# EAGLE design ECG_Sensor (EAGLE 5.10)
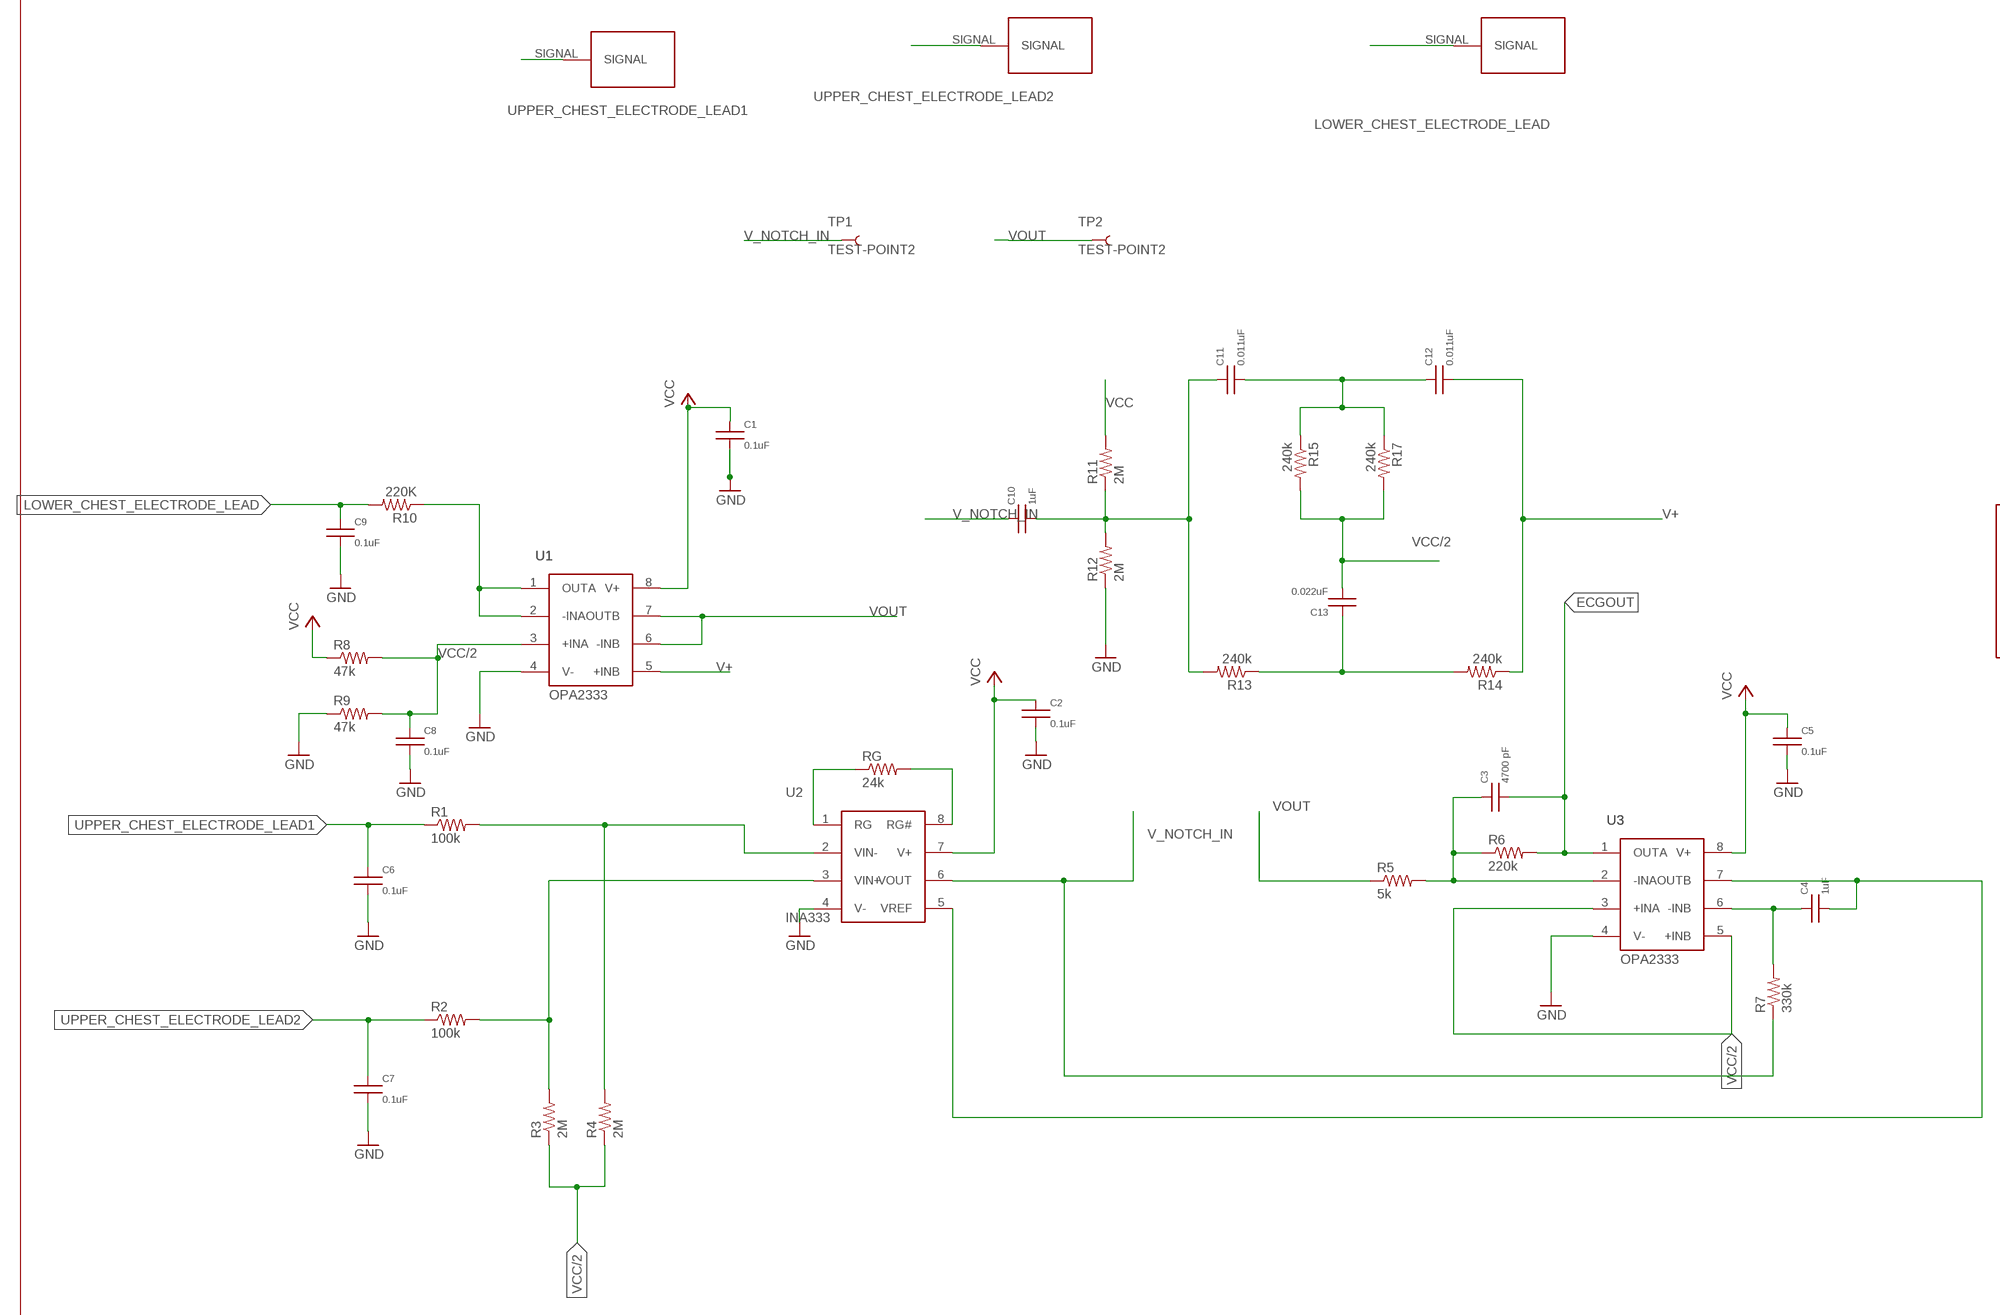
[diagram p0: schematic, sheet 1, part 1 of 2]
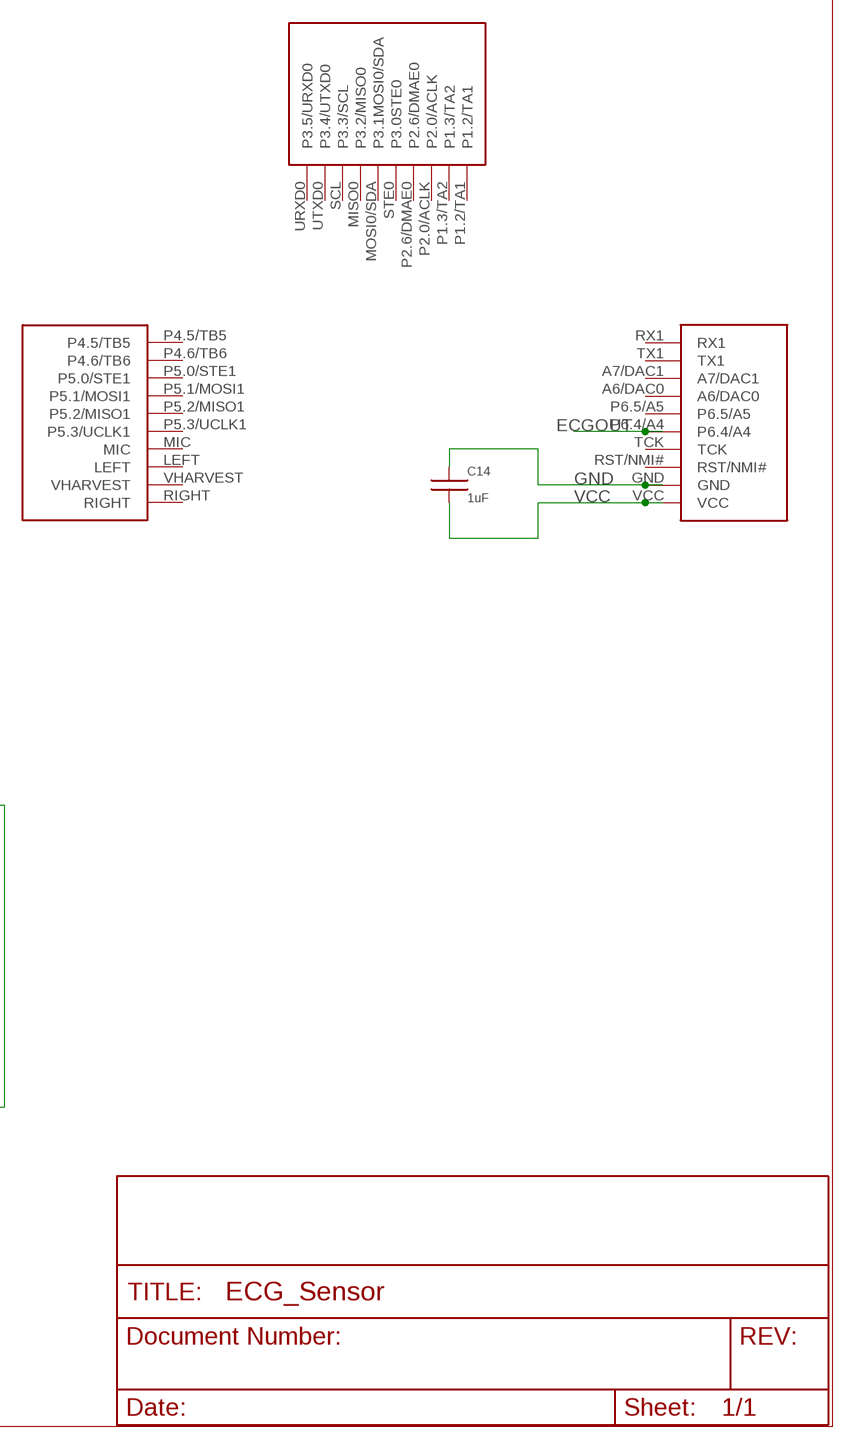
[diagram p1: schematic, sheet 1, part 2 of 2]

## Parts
BLACK  PLASTICJACKNEW  [PLASTICJACKNEW]
C1  0.1uF  C0603  [C0603]
C2  0.1uF  C0603  [C0603]
C3  4700 pF  C0603  [C0603]
C4  1uF  C0603  [C0603]
C5  0.1uF  C0603  [C0603]
C6  0.1uF  C0603  [C0603]
C7  0.1uF  C0603  [C0603]
C8  0.1uF  C0603  [C0603]
C9  0.1uF  C0603  [C0603]
C10  1uF  C0603  [C0603]
C11  0.011uF  C1206  [C1206]
C12  0.011uF  C1206  [C1206]
C13  0.022uF  C1206  [C1206]
C14  1uF  C0603  [C0603]
J4  HIJACK-INTERFACE  [HIJACK-INTERFACE-30PIN]
R1  100k  R-US_R0603  [R0603]
R2  100k  R-US_R0603  [R0603]
R3  2M  R-US_R0603  [R0603]
R4  2M  R-US_R0603  [R0603]
R5  5k  R-US_R0603  [R0603]
R6  220k  R-US_R0603  [R0603]
R7  330k  R-US_R0603  [R0603]
R8  47k  R-US_R0603  [R0603]
R9  47k  R-US_R0603  [R0603]
R10  220K  R-US_R0603  [R0603]
R11  2M  R-US_R0603  [R0603]
R12  2M  R-US_R0603  [R0603]
R13  240k  R-US_R0603  [R0603]
R14  240k  R-US_R0603  [R0603]
R15  240k  R-US_R0603  [R0603]
R17  240k  R-US_R0603  [R0603]
RED  PLASTICJACKNEW  [PLASTICJACKNEW]
RG  24k  R-US_R0603  [R0603]
TP1  TEST-POINT2  [PAD.02X.02]
TP2  TEST-POINT2  [PAD.02X.02]
U1  OPA2333  [SOIC]
U2  INA333  [MSOP8]
U3  OPA2333  [SOIC]
WHITE  PLASTICJACKNEW  [PLASTICJACKNEW]

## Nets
ECGOUT: C3.2 J4.P6.4/A4 R6.2 U3.1(OUTA)
GND: C1.2 C2.2 C5.2 C6.2 C7.2 C8.2 C9.2 C14.1 J4.GND R9.1 R12.1 U1.4(V-) U2.4(V-) U3.4(V-)
LOWER_CHEST_ELECTRODE_LEAD: BLACK.SIGNAL C9.1 R10.2
N$2: R10.1 U1.1(OUTA) U1.2(-INA)
N$4: RG.1 U2.1(RG)
N$5: RG.2 U2.8(RG#)
N$6: R1.2 R4.2 U2.2(VIN-)
N$7: C11.2 C12.1 R15.1 R17.1
N$8: R2.2 R3.2 U2.3(VIN+)
N$10: C10.2 C11.1 R11.1 R12.2 R13.2
N$12: C13.1 R13.1 R14.2
N$13: C3.1 R5.2 R6.1 U3.2(-INA)
N$17: C4.1 R7.2 U3.6(-INB)
UPPER_CHEST_ELECTRODE_LEAD1: C6.1 R1.1 RED.SIGNAL
UPPER_CHEST_ELECTRODE_LEAD2: C7.1 R2.1 WHITE.SIGNAL
V+: C12.2 R14.1 U1.5(+INB)
V_NOTCH_IN: C10.1 R7.1 TP1.P$1 U2.6(VOUT)
VCC: C1.1 C2.1 C5.1 C14.2 J4.VCC R8.1 R11.2 U1.8(V+) U2.7(V+) U3.8(V+)
VCC/2: C8.1 C13.2 R3.1 R4.1 R8.2 R9.2 R15.2 R17.2 U1.3(+INA) U3.3(+INA) U3.5(+INB)
VOUT: R5.1 TP2.P$1 U1.6(-INB) U1.7(OUTB)
VREF: C4.2 U2.5(VREF) U3.7(OUTB)
Unconnected: J4.A6/DAC0 J4.A7/DAC1 J4.LEFT J4.MIC J4.MISO0(P3.2/MISO0) J4.MOSI0/SDA(P3.1MOSI0/SDA) J4.P1.2/TA1 J4.P1.3/TA2 J4.P2.0/ACLK J4.P2.6/DMAE0 J4.P4.5/TB5 J4.P4.6/TB6 J4.P5.0/STE1 J4.P5.1/MOSI1 J4.P5.2/MISO1 J4.P5.3/UCLK1 J4.P6.5/A5 J4.RIGHT J4.RST/NMI# J4.RX1 J4.SCL(P3.3/SCL) J4.STE0(P3.0STE0) J4.TCK J4.TX1 J4.URXD0(P3.5/URXD0) J4.UTXD0(P3.4/UTXD0) J4.VHARVEST

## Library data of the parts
BLACK RED WHITE = sonal:PLASTICJACKNEW
C1-C14 = umich:C
J4 = umich:HIJACK-INTERFACE
R1-R15 R17 RG = rcl:R-US_: RESISTOR, American symbol
TP1 TP2 = SparkFun:TEST-POINT
U1 U3 = sonal:OPA2333
U2 = sonal:INA333

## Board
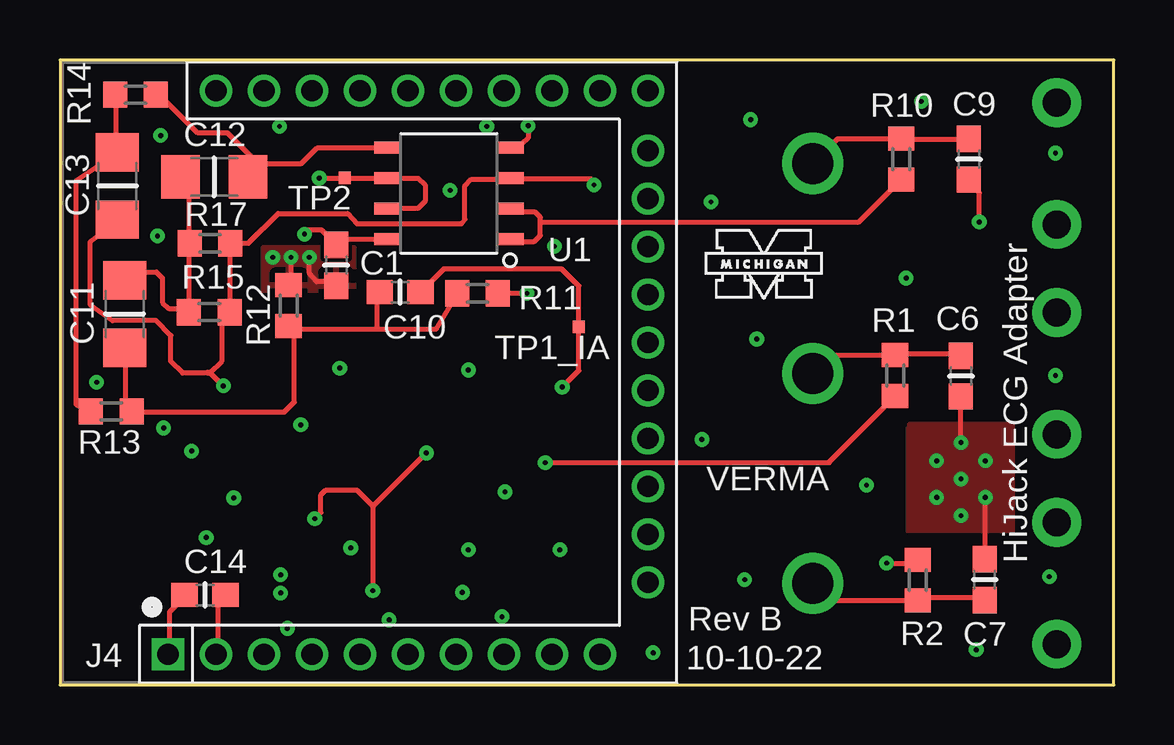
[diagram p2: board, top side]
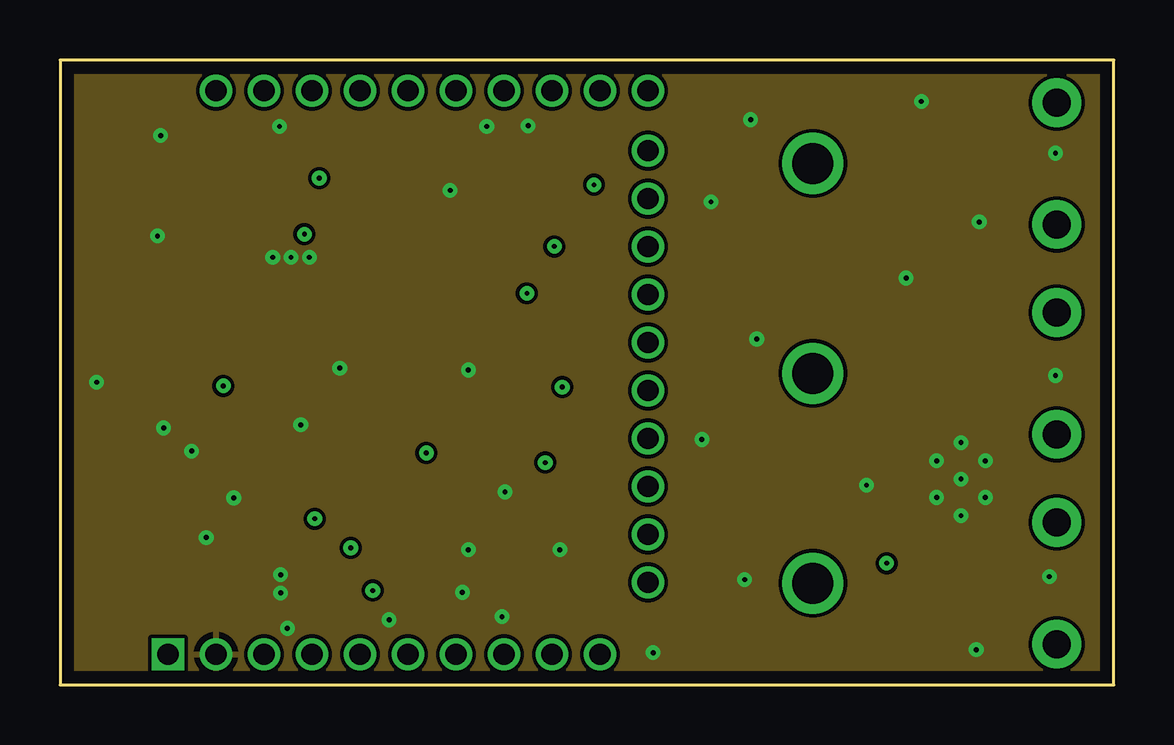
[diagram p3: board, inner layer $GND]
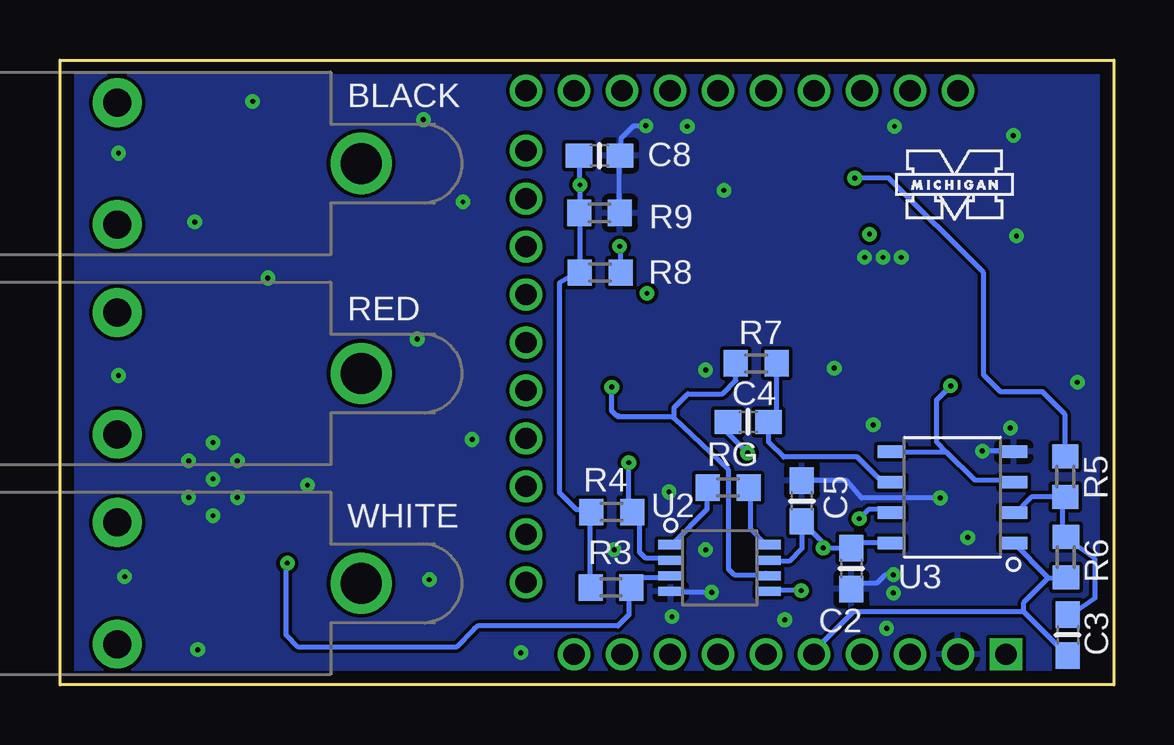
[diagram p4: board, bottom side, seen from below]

Size 43.92 x 26.06 mm. Coordinates in mm from the lower left corner, seen from the top.
Outline: 0,0 43.92,0 43.92,26.06 0,26.06 0,0
Copper layers (1+2*15+16): Top 0.0178mm / dielectric 0.3048mm / $GND 0.0356mm / dielectric 0.7112mm / $VCC 0.0356mm / dielectric 0.3048mm / Bottom 0.0178mm
Design rules "SSC-EAGLE-4Lyr_v1.0.0.3": minimum track width 6mil, minimum drill 8mil, track to track 6mil, track to pad 6mil, pad to pad 6mil, via to via 6mil, smd to smd 6mil, copper to edge 20mil, drill to drill 16mil, minimum pad ring 8mil, minimum via ring 8mil, stop-mask expansion 3mil, vias tented up to drill 0mil, thermal gap 10mil

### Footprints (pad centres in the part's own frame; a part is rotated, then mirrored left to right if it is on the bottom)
PLASTICJACKNEW = drill 1.168 pad 2.032 round: P$1 2.286,2.54; P$2 2.286,-2.54 | drill 1.702 pad 2.54 round: SIGNAL -7.874,0
C0603 = smd 1.1 x 1: 1 -0.85,0; 2 0.85,0
C1206 = smd 1.6 x 1.8: 1 -1.4,0; 2 1.4,0
HIJACK-INTERFACE-30PIN = drill 0.89 pad 1.346 round: A6/DAC0 2.89,-12.46; A7/DAC1 4.89,-12.46; GND -7.11,-12.46; LEFT -3.11,11.04; MIC -1.11,11.04; MISO0 10.89,2.54; MOSI0/SDA 10.89,0.54; P1.2/TA1 10.89,-9.46; P1.3/TA2 10.89,-7.46; P2.0/ACLK 10.89,-5.46; P2.6/DMAE0 10.89,-3.46; P4.5/TB5 10.89,11.04; P4.6/TB6 8.89,11.04; P5.0/STE1 6.89,11.04; P5.1/MOSI1 4.89,11.04; P5.2/MISO1 2.89,11.04; P5.3/UCLK1 0.89,11.04; P6.4/A4 -1.11,-12.46; P6.5/A5 0.89,-12.46; RIGHT -7.11,11.04; RST/NMI# -5.11,-12.46; RX1 8.89,-12.46; SCL 10.89,4.54; STE0 10.89,-1.46; TCK -3.11,-12.46; TX1 6.89,-12.46; URXD0 10.89,8.54; UTXD0 10.89,6.54; VHARVEST -5.11,11.04 | drill 0.89 pad 1.346 square: VCC -9.11,-12.46
R0603 = smd 1 x 1.1: 1 -0.85,0; 2 0.85,0
PAD.02X.02 = smd 0.508 x 0.508: P$1 0,0
SOIC = smd 0.51 x 1.143: 1 -1.905,-2.55; 2 -0.635,-2.55; 3 0.635,-2.55; 4 1.905,-2.55; 5 1.905,2.55; 6 0.635,2.55; 7 -0.635,2.55; 8 -1.905,2.55
MSOP8 = smd 0.38 x 1.016: 1 -0.975,-2.038; 2 -0.325,-2.038; 3 0.325,-2.038; 4 0.975,-2.038; 5 0.975,2.038; 6 0.325,2.038; 7 -0.325,2.038; 8 -0.975,2.038

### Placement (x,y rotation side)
BLACK  39.24,21.74 180 bottom
C1  11.51,17.5 270 top
C2  10.95,4.85 270 bottom
C3  1.93,2.08 270 bottom
C4  15.24,10.97 180 bottom
C5  13,7.67 90 bottom
C6  37.54,12.88 270 top
C7  38.53,4.39 90 top
C8  21.44,22.07 0 bottom
C9  37.87,21.92 270 top
C10  14.17,16.38 180 top
C11  2.69,15.47 90 top
C12  6.43,21.18 0 top
C13  2.39,20.8 270 top
C14  6.05,3.76 180 top
J4  13.61,13.74 0 top
R1  34.8,12.9 270 top
R2  35.74,4.37 90 top
R3  20.95,4.06 0 bottom
R4  20.93,7.21 0 bottom
R5  2.03,8.69 270 bottom
R6  2.01,5.33 270 bottom
R7  14.91,13.41 0 bottom
R8  21.41,17.2 180 bottom
R9  21.44,19.69 180 bottom
R10  35.05,21.92 90 top
R11  17.4,16.33 0 top
R12  9.52,15.82 270 top
R13  2.13,11.4 0 top
R14  3.15,24.61 180 top
R15  6.22,15.54 0 top
R17  6.25,18.41 0 top
RED  39.24,12.99 180 bottom
RG  16.08,8.23 0 bottom
TP1  21.62,14.94 0 top
TP2  11.86,21.14 0 top
U1  16.21,20.5 90 top
U2  16.43,4.88 270 bottom
U3  6.73,7.82 90 bottom
U$1  [UMICH]  26.8,15.9 0 top
U$2  [UMICH]  9.17,19.2 0 bottom
WHITE  39.24,4.24 180 bottom

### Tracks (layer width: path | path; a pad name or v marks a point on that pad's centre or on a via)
ECGOUT
  Bottom 0.203: 3.76,3.05 1.93,1.22 C3.2 | 4.17,5.89 U3.1 2.73,4.47 | R6.2 2.13,4.47 2.73,4.47 | 3.76,3.05 10.87,3.05 12.5,1.42 J4.P6.4/A4 | 2.73,4.47 3.76,3.44 3.76,3.05
GND  (via drill 0.2)
  Top 0.203: C6.2 37.69,11.99 37.54,11.84 v37.54,10.11 | 38.51,5.28 C7.2 38.56,5.27 v38.56,7.82 | C9.2 37.9,20.93 38.3,20.52 v38.3,19.3 | J4.GND 6.6,1.42 6.6,3.45 6.81,3.66 C14.1 7.01,3.86 | v19.51,23.32 19.51,22.81 18.97,22.3 18.59,22.56 U1.4 | R12.1 9.63,16.67 v9.63,17.83 | C1.2 11.51,16.71 11.4,16.82 10.69,16.82 10.39,17.17 v10.39,17.83
  Bottom 0.203: v16.76,3.86 18.39,3.86 U2.4 | R9.1 20.63,19.71 20.63,21.95 C8.2 20.42,22.15 20.52,22.25 20.52,22.81 20.02,23.32 v19.51,23.32 19.52,23.13 | v5.49,9.75 4.17,9.75 U3.4 | v9.2,4.6 9.53,4.6 9.86,4.27 10.68,4.27 C2.2 | v7.24,7.8 10.52,7.8 11.14,8.52 C5.2
  other vias: 36.53,9.35 37.54,8.59 38.56,9.35 36.53,7.82 37.54,7.06 9.19,3.84 8.86,17.83 17.02,5.64 18.54,8.05 20.83,5.64 11.65,13.21 6.1,6.15 4.32,10.72 17.78,23.29 9.14,23.29 4.19,22.91 4.06,18.72 10.03,10.85 1.52,12.62 28.52,4.39 24.71,1.35 38.18,1.47 41.22,4.52 41.48,12.9 41.48,22.17 28.78,23.57 29.03,14.43 35.26,16.97 33.6,8.33 26.75,10.24 35.89,24.33 17.02,13.13 16.26,20.62 27.13,20.14 9.47,2.36 18.41,2.84 13.72,2.72
  pour $GND: 0.28,25.83 43.69,25.83 43.61,0.15 0.36,0.25
  pour Top: 35.41,10.9 39.73,10.9 39.73,6.4 35.31,6.4 35.31,10.72 35.36,10.72 35.36,10.87
  pour Bottom: 8.59,4.9 9.86,4.9 9.86,3.51 8.59,3.51
  pour Top: 8.46,18.24 8.46,16.46 12.27,16.46 12.27,18.24
  pour Bottom: 43.74,25.76 43.74,25.7 43.69,25.7 43.69,0.2 0.36,0.2 0.28,25.81
LOWER_CHEST_ELECTRODE_LEAD
  Top 0.203: C9.1 37.69,22.76 R10.2 32.4,22.77 BLACK.SIGNAL
N$2
  Top 0.203: 18.8,18.69 U1.1 18.86,18.49 19.76,18.49 20.02,18.75 20.02,19.3 | U1.2 18.8,19.71 19.81,19.71 20.02,19.51 20.02,19.3 | 35.05,20.93 R10.1 33.29,19.3 20.02,19.3
N$4
  Bottom 0.203: U2.1 18.39,5.89 16.97,7.32 16.97,8.13 RG.1
N$5
  Bottom 0.203: U2.8 14.53,5.89 15.14,6.5 15.14,8.13 RG.2
N$6  (via drill 0.2)
  Top 0.203: 34.47,11.99 34.65,11.99 R1.2 32.06,9.31 32.06,9.27 v20.22,9.27
  Bottom 0.203: U2.2 18.59,5.28 19.51,5.28 19.76,5.54 19.76,6.9 R4.2 | R4.2 20.02,7.11 | v20.22,9.27 20.22,7.32 R4.2
N$7
  Top 0.203: C11.2 2.74,16.87 2.9,16.87 3.25,17.22 4.01,17.22 4.27,16.97 4.27,15.95 4.52,15.7 5.22,15.7 R15.1 5.39,15.65 5.39,18.49 R17.1 5.39,18.69 5.39,20.93 5.18,21.13 C12.1
N$8  (via drill 0.2)
  Top 0.203: v34.44,5.08 35.66,5.08 R2.2
  Bottom 0.203: U2.3 18.59,4.47 20.02,4.47 20.02,4.06 R3.2 20.22,4.06 20.22,2.92 20.68,2.46 26.52,2.46 26.67,2.31 | v34.44,5.08 34.49,5.03 34.49,2.08 33.99,1.58 27.41,1.58 26.67,2.31 | 26.67,2.31 26.67,2.34
N$10
  Top 0.203: C11.1 2.74,14.02 2.74,11.79 2.95,11.58 R13.2 3.15,11.38 9.35,11.38 9.77,11.8 9.77,14.73 arc90 R12.2 9.65,14.85 13.22,14.85 | 16.36,16.26 R11.1 16.55,16.3 15.68,14.85 13.22,14.85 | C10.2 13.22,16.28 13.22,14.85
N$12
  Top 0.203: R13.1 0.69,11.68 0.69,21.03 2.34,22.15 C13.1 2.34,22.35 2.34,24.59 R14.2
N$13
  Bottom 0.203: C3.1 1.93,2.85 0.79,3.63 0.79,5.26 1.93,6.1 R6.1 2.13,6.3 2.13,7.72 R5.2 3.44,7.84 4.17,7.11 U3.2
N$17
  Bottom 0.203: U3.6 9.45,8.53 9.73,8.53 10.69,9.5 13.77,9.5 14.39,10.12 C4.1 | C4.1 14.53,10.97 | C4.1 14.25,10.83 | C4.1 14.06,10.97 R7.2
UPPER_CHEST_ELECTRODE_LEAD1
  Top 0.203: R1.1 34.85,13.82 37.49,13.82 C6.1 | R1.1 34.65,13.61 | RED.SIGNAL 32.13,13.75 R1.1
UPPER_CHEST_ELECTRODE_LEAD2
  Top 0.203: R2.1 35.87,3.66 38.51,3.66 C7.1 | R2.1 35.66,3.66 | WHITE.SIGNAL 32.09,3.52 R2.1
V+
  Top 0.203: 8.03,21.74 10.06,21.74 10.72,22.4 U1.5 | 8.03,21.74 8.03,21.34 C12.2 7.82,21.34 7.42,21.34 | R14.1 4.17,24.59 5.74,23.01 6.99,23.01 8.03,21.97 8.03,21.74
V_NOTCH_IN  (via drill 0.2)
  Top 0.203: C10.1 15.99,17.35 20.9,17.35 21.62,16.64 TP1.P$1 21.62,13.11 v20.93,12.42
  Bottom 0.203: 18.33,11.12 16.05,8.97 16.05,4.83 15.8,4.57 14.42,4.57 U2.6 14.53,4.67 | 18.33,11.12 18.39,11.18 20.6,11.18 | 20.6,11.18 20.65,11.23 20.73,11.23 20.93,11.43 v20.93,12.42 20.93,12.27 | 20.68,11.18 20.65,11.2 20.63,11.18 20.6,11.18 | R7.1 15.76,12.69 16.31,12.14 17.75,12.14 18.33,11.57 18.33,11.12
VCC  (via drill 0.2)
  Top 0.203: R11.2 18.19,16.46 | 13.72,18.49 U1.8 11.75,18.59 C1.1 11.51,18.36 10.9,18.97 10.36,18.97 v10.19,18.8 | J4.VCC 4.57,1.42 4.57,3.05 5.18,3.66 C14.2 5.39,3.86 | R11.2 18.19,16.26 | R11.2 v19.46,16.33
  Bottom 0.203: 14.33,5.28 U2.7 14.35,5.16 13.54,5.16 13.01,5.69 C5.1 12.12,5.93 v12.12,5.72 12.1,5.7 C2.1 10.96,5.72 10.76,5.92 U3.8 | 20.42,17.07 R8.1 20.56,18.25 v20.6,18.29
VCC/2  (via drill 0.2)
  Top 0.203: v22.25,20.85 22.12,21.11 18.78,21.11 U1.3 18.7,21.08 17.15,21.08 16.87,20.8 16.87,19.41 16.74,19.23 12.37,19.23 11.99,19.66 9.09,19.66 7.85,18.42 R17.2 7.1,15.55 R15.2 | C13.2 2.34,19.3 1.27,18.49 1.27,15.85 2.18,15.19 4.01,15.19 4.62,14.58 4.62,13.49 5.11,13.01 6.17,13.01 | R15.2 7.01,15.44 | R15.2 6.88,15.36 | R15.2 6.76,15.23 6.76,13.51 6.25,13.01 6.17,13.01 | 6.17,13.01 6.15,13.03 6.25,13.03 v6.81,12.47
  Bottom 0.203: U3.3 4.37,8.53 5.79,8.53 6.96,9.7 | 9.25,9.75 U3.5 9.26,9.7 6.96,9.7 | R3.1 21.84,4.06 21.84,7.11 R4.1 21.84,7.32 22.4,7.32 23.11,8.03 23.11,16.76 22.61,17.07 22.45,17.07 R8.2 22.25,17.27 22.25,19.51 R9.2 22.25,19.71 v22.25,20.85 | C8.1 22.25,21.95 v22.25,20.85 | v22.25,20.85 22.25,20.93 | 6.96,9.7 7.39,10.13 7.39,11.89 v6.81,12.47
VOUT  (via drill 0.2)
  Top 0.203: U1.6 14.94,21.13 15.21,20.85 15.21,20.17 14.91,19.86 U1.7 | U1.6 13.61,21.13 13.61,21.16 | U1.6 11.9,21.13 TP2.P$1 v10.8,21.14
  Bottom 0.203: R5.1 2.03,11.28 2.97,12.22 4.72,12.22 5.44,12.93 5.44,17.2 9.38,21.14 v10.8,21.14
VREF  (via drill 0.2)
  Top 0.203: v10.62,6.93 10.87,7.19 10.87,7.93 11.07,8.13 12.37,8.13 13.03,7.47 | 13.03,7.47 v13.03,3.94 | 13.03,7.47 13.06,7.47 v15.27,9.68
  Bottom 0.203: 14.34,3.96 U2.5 14.36,3.94 v13.03,3.94 | U3.7 9.45,7.32 10.24,7.32 v10.62,6.93 | C4.2 16.09,10.5 v15.27,9.68 15.29,9.65

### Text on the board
tPlace: TP2 | TP1_IA | VERMA | HiJack ECG Adapter | Rev B | 10-10-22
